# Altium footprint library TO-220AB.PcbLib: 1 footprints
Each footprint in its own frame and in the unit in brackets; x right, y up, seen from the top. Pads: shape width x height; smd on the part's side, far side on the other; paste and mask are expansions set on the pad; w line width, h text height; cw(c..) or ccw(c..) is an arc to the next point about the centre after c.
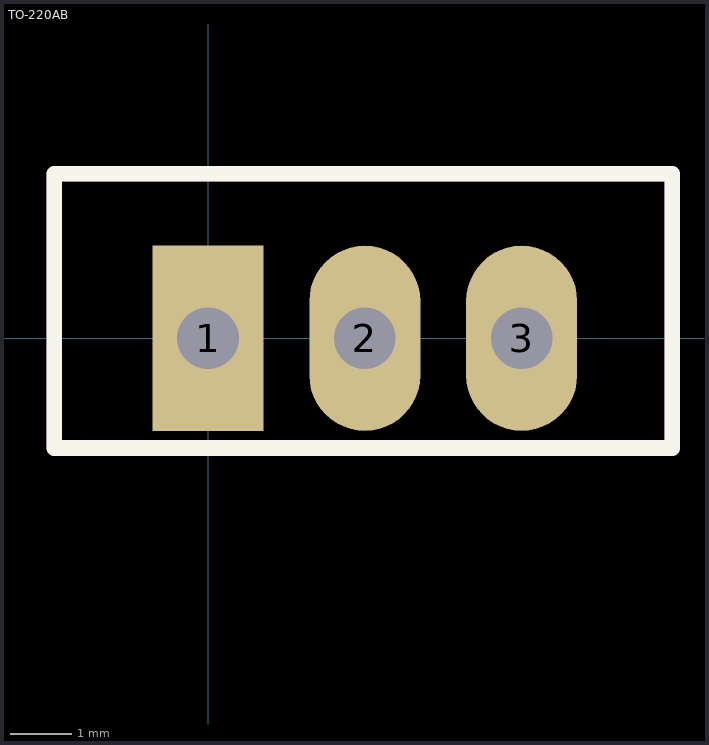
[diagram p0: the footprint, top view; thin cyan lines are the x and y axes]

## TO-220AB [mm]
pads (3):
  rect 1.8x3 hole 1: 1(0,0)
  oval 1.8x3 hole 1: 2(2.54,0) 3(5.08,0)
Top Overlay:
  lines w0.254: 6.426,2.667 -1.143,2.667 ; -1.143,2.667 7.518,2.667 7.518,1.372 7.518,-1.778 -2.489,-1.778 -2.489,2.667 -1.143,2.667
Mechanical 15:
  lines w0.254: 6.426,2.667 -1.143,2.667 ; -1.143,2.667 -2.489,2.667 -2.489,-1.778 7.518,-1.778 7.518,1.372 7.518,2.667 -1.143,2.667
3D body "User Library-TO-220-4.STEP": height 20.06, standoff -8.74, extent -2.56,-1.778 7.64,2.722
